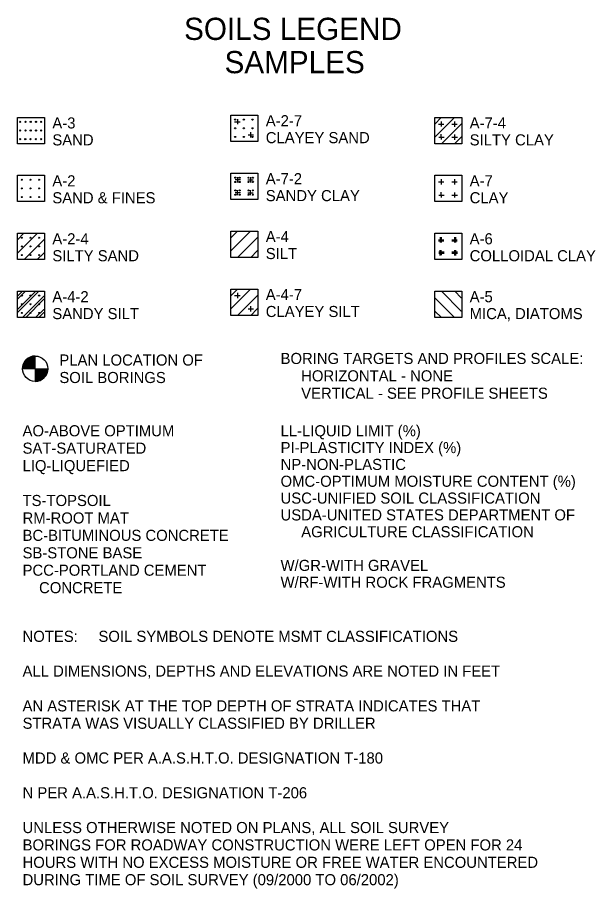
# Model space of a CAD drawing. Extents: x 1.3 to 42.5, y 0 to 21.2.
# Drawn here: x 36.22 to 42.47, y 11.81 to 21.24 of the extents above; entities that cross this region are included whole.
import ezdxf

# ---------------------------------------------------------------- set-up
doc = ezdxf.new("R2010")
doc.units = 0
doc.layers.add('SOIL-TEXT', color=7, linetype='Continuous')

msp = doc.modelspace()

# ---------------------------------------------------------------- linework, layer by layer
at = {"layer": 'SOIL-TEXT'}
for p, q in [((38.5684, 20.107), (38.6266, 20.107)), ((40.8022, 20.1541), (40.7317, 20.0819)), ((40.9453, 20.1531), (40.7317, 19.9395)), ((40.7726, 20.0823), (40.8309, 20.0823)), ((41.0164, 20.0819), (40.8041, 19.8696)), ((40.9147, 20.0819), (40.9729, 20.0819)), ((40.9453, 20.11), (40.9453, 20.0531)), ((41.0238, 20.0892), (41.0167, 20.0819)), ((38.7131, 19.9642), (38.7713, 19.9642)), ((40.7747, 19.9395), (40.833, 19.9395)), ((40.8028, 19.9146), (40.8026, 19.9715)), ((40.9173, 19.9395), (40.9756, 19.9395)), ((41.0164, 19.9395), (40.9465, 19.8696)), ((41.0238, 19.9467), (41.0167, 19.9395)), ((38.6003, 19.5082), (38.6003, 19.4513)), ((38.741, 19.5082), (38.741, 19.4513)), ((38.6309, 19.48), (38.5727, 19.48)), ((38.7104, 19.48), (38.7687, 19.48)), ((40.7726, 19.4569), (40.8309, 19.4569)), ((40.9147, 19.4564), (40.9729, 19.4564)), ((40.9453, 19.4846), (40.9453, 19.4277)), ((38.6309, 19.3401), (38.5727, 19.3401)), ((38.6003, 19.3119), (38.6003, 19.3688)), ((38.7092, 19.3401), (38.7675, 19.3401)), ((38.7398, 19.3119), (38.7398, 19.3688)), ((40.7747, 19.314), (40.833, 19.314)), ((40.8028, 19.2892), (40.8026, 19.3461)), ((40.9173, 19.3141), (40.9756, 19.3141)), ((36.291, 18.9011), (36.2204, 18.8289)), ((36.434, 18.9001), (36.2204, 18.6865)), ((38.598, 18.9247), (38.5274, 18.8525)), ((38.741, 18.9237), (38.5274, 18.7101)), ((38.8122, 18.8525), (38.5999, 18.6402)), ((38.8196, 18.8598), (38.8124, 18.8525)), ((40.9453, 18.8581), (40.9453, 18.8012)), ((40.9566, 18.8581), (40.9566, 18.8012)), ((36.5052, 18.8289), (36.2929, 18.6166)), ((36.5126, 18.8362), (36.5054, 18.8289)), ((40.7726, 18.8304), (40.8309, 18.8304)), ((40.7726, 18.819), (40.8309, 18.819)), ((40.9147, 18.8299), (40.9729, 18.8299)), ((40.9147, 18.8186), (40.9729, 18.8186)), ((36.5052, 18.6865), (36.4353, 18.6166)), ((36.5126, 18.6937), (36.5054, 18.6865)), ((38.8122, 18.7101), (38.7423, 18.6402)), ((38.8196, 18.7173), (38.8124, 18.7101)), ((40.7747, 18.699), (40.833, 18.699)), ((40.7747, 18.6876), (40.833, 18.6876)), ((40.7914, 18.6626), (40.7913, 18.7195)), ((40.8028, 18.6627), (40.8026, 18.7196)), ((40.9173, 18.699), (40.9756, 18.699)), ((40.9173, 18.6876), (40.9756, 18.6876)), ((38.598, 18.2983), (38.5274, 18.226)), ((38.741, 18.2972), (38.5274, 18.0836)), ((36.4188, 18.2746), (36.2204, 18.0762)), ((36.2739, 18.2735), (36.2211, 18.2195)), ((36.45, 18.2736), (36.2219, 18.0455)), ((36.3069, 18.2747), (36.2224, 18.1882)), ((36.5075, 18.2209), (36.279, 17.9924)), ((36.5061, 18.1873), (36.3106, 17.9918)), ((36.5126, 18.2237), (36.5084, 18.2195)), ((36.5126, 18.1911), (36.5097, 18.1882)), ((38.5684, 18.2265), (38.6266, 18.2265)), ((38.8122, 18.226), (38.5999, 18.0137)), ((38.8196, 18.2334), (38.8124, 18.226)), ((40.7336, 18.2024), (40.9459, 17.9901)), ((40.8048, 18.2736), (41.0184, 18.06)), ((40.9478, 18.2747), (41.0184, 18.2024)), ((41.0206, 18.2024), (41.0238, 18.1991)), ((38.8196, 18.0908), (38.8124, 18.0836)), ((36.5062, 18.0773), (36.4211, 17.9922)), ((36.5053, 18.0442), (36.4523, 17.9911)), ((36.5126, 18.0811), (36.5077, 18.0762)), ((36.5126, 18.0489), (36.5092, 18.0455)), ((38.7131, 18.0837), (38.7713, 18.0837)), ((38.8122, 18.0836), (38.7423, 18.0137)), ((40.7336, 18.06), (40.8035, 17.9901)), ((41.0206, 18.06), (41.0238, 18.0568)), ((36.4127, 17.4362), (36.4127, 17.5732)), ((36.4127, 17.4362), (36.2761, 17.4362)), ((36.4127, 17.4362), (36.4127, 17.4362)), ((36.4127, 17.4362), (36.4127, 17.2996)), ((36.4127, 17.4362), (36.5493, 17.4362))]:
    msp.add_line(p, q, dxfattribs=at)
for points in [[(38.5274, 20.1779), (38.8196, 20.1779), (38.8196, 19.8932), (38.5274, 19.8932)], [(36.2204, 20.1543), (36.5126, 20.1543), (36.5126, 19.8696), (36.2204, 19.8696)], [(40.7317, 20.1543), (41.0238, 20.1543), (41.0238, 19.8696), (40.7317, 19.8696)], [(36.2204, 19.5278), (36.5126, 19.5278), (36.5126, 19.2431), (36.2204, 19.2431)], [(38.5274, 19.5515), (38.8196, 19.5515), (38.8196, 19.2667), (38.5274, 19.2667)], [(40.7317, 19.5278), (41.0238, 19.5278), (41.0238, 19.2431), (40.7317, 19.2431)], [(36.2204, 18.9014), (36.5126, 18.9014), (36.5126, 18.6166), (36.2204, 18.6166)], [(38.5274, 18.925), (38.8196, 18.925), (38.8196, 18.6402), (38.5274, 18.6402)], [(40.7317, 18.9014), (41.0238, 18.9014), (41.0238, 18.6166), (40.7317, 18.6166)], [(38.5274, 18.2985), (38.8196, 18.2985), (38.8196, 18.0137), (38.5274, 18.0137)], [(36.2204, 18.2749), (36.5126, 18.2749), (36.5126, 17.9902), (36.2204, 17.9902)], [(40.7317, 18.2749), (41.0238, 18.2749), (41.0238, 17.9901), (40.7317, 17.9901)]]:
    msp.add_lwpolyline(points, close=True, dxfattribs=at)
for points in [[(38.5978, 20.1364), (38.5981, 20.1135), (38.5978, 20.0795)], [(40.802, 20.1117), (40.8023, 20.0889), (40.802, 20.0548)], [(38.7409, 19.9936), (38.7412, 19.9708), (38.7409, 19.9367)], [(40.9452, 19.9689), (40.9455, 19.9461), (40.9452, 19.912)], [(40.802, 19.4863), (40.8023, 19.4634), (40.802, 19.4294)], [(40.9452, 19.3435), (40.9455, 19.3207), (40.9452, 19.2866)], [(40.7906, 18.8597), (40.7909, 18.8369), (40.7906, 18.803)], [(40.802, 18.8598), (40.8023, 18.837), (40.802, 18.8029)], [(40.9452, 18.717), (40.9455, 18.6942), (40.9452, 18.6601)], [(40.9566, 18.7171), (40.9569, 18.6942), (40.9566, 18.66)], [(38.5978, 18.2559), (38.5981, 18.233), (38.5978, 18.199)], [(38.7409, 18.1131), (38.7412, 18.0903), (38.7409, 18.0562)]]:
    msp.add_lwpolyline(points, dxfattribs=at)
for centre, radius in [((36.2499, 20.1063), 0.0057), ((36.3068, 20.1063), 0.0057), ((36.3638, 20.1063), 0.0057), ((36.4207, 20.1063), 0.0057), ((36.4777, 20.1063), 0.0057), ((38.574, 20.1299), 0.0057), ((38.6677, 20.1299), 0.0057), ((38.7613, 20.1299), 0.0057), ((36.2499, 20.0127), 0.0057), ((36.3068, 20.0127), 0.0057), ((36.3638, 20.0127), 0.0057), ((36.4207, 20.0127), 0.0057), ((36.4777, 20.0127), 0.0057), ((38.574, 20.0363), 0.0057), ((38.6677, 20.0363), 0.0057), ((38.7613, 20.0363), 0.0057), ((36.2489, 19.9191), 0.0057), ((36.3058, 19.9191), 0.0057), ((36.3628, 19.9191), 0.0057), ((36.4197, 19.9191), 0.0057), ((36.4767, 19.9191), 0.0057), ((38.574, 19.9426), 0.0057), ((38.6677, 19.9426), 0.0057), ((38.7613, 19.9426), 0.0057), ((38.576, 19.5022), 0.0057), ((38.6225, 19.5021), 0.0057), ((38.7189, 19.5021), 0.0057), ((38.7654, 19.5022), 0.0057), ((36.267, 19.4798), 0.0057), ((36.3606, 19.4798), 0.0057), ((36.4543, 19.4798), 0.0057), ((38.576, 19.4557), 0.0057), ((38.6225, 19.4557), 0.0057), ((38.7189, 19.4557), 0.0057), ((38.7654, 19.4557), 0.0057), ((36.267, 19.3862), 0.0057), ((36.3606, 19.3862), 0.0057), ((36.4543, 19.3862), 0.0057), ((38.576, 19.3644), 0.0057), ((38.576, 19.3179), 0.0057), ((38.6225, 19.3644), 0.0057), ((38.6225, 19.318), 0.0057), ((38.7177, 19.3644), 0.0057), ((38.7177, 19.318), 0.0057), ((38.7642, 19.3644), 0.0057), ((38.7642, 19.3179), 0.0057), ((36.267, 19.2925), 0.0057), ((36.3606, 19.2925), 0.0057), ((36.4543, 19.2925), 0.0057), ((36.267, 18.8523), 0.0057), ((36.3606, 18.8523), 0.0057), ((36.4543, 18.8523), 0.0057), ((36.267, 18.7586), 0.0057), ((36.3606, 18.7586), 0.0057), ((36.4543, 18.7586), 0.0057), ((36.267, 18.665), 0.0057), ((36.3606, 18.665), 0.0057), ((36.4543, 18.665), 0.0057), ((36.268, 18.2268), 0.0057), ((36.3616, 18.2268), 0.0057), ((36.4552, 18.2268), 0.0057), ((36.268, 18.1332), 0.0057), ((36.3616, 18.1332), 0.0057), ((36.4552, 18.1332), 0.0057), ((36.268, 18.0395), 0.0057), ((36.3616, 18.0395), 0.0057), ((36.4552, 18.0395), 0.0057), ((36.4124, 17.4364), 0.1367)]:
    msp.add_circle(centre, radius, dxfattribs=at)
for radius, start, end in [(0.1367, 90.0009, 180.0009), (0.1338, 90.0009, 180.0009), (0.131, 90.0009, 180.0009), (0.1281, 90.0009, 180.0009), (0.1253, 90.0009, 180.0009), (0.1224, 90.0009, 180.0009), (0.1196, 90.0009, 180.0009), (0.1168, 90.0009, 180.0009), (0.1139, 90.0009, 180.0009), (0.1111, 90.0009, 180.0009), (0.1082, 90.0009, 180.0009), (0.1054, 90.0009, 180.0009), (0.1025, 90.0009, 180.0009), (0.0997, 90.0009, 180.0009), (0.0968, 90.0009, 180.0009), (0.094, 90.0009, 180.0009), (0.0911, 90.0009, 180.0009), (0.0883, 90.0009, 180.0009), (0.0854, 90.0009, 180.0009), (0.0826, 90.0009, 180.0009), (0.0797, 90.0009, 180.0009), (0.0769, 90.0009, 180.0009), (0.074, 90.0009, 180.0009), (0.0712, 90.0009, 180.0009), (0.0683, 90.0009, 180.0009), (0.0655, 90.0009, 180.0009), (0.0626, 90.0009, 180.0009), (0.0598, 90.0009, 180.0009), (0.057, 90.0009, 180.0009), (0.0541, 90.0009, 180.0009), (0.0513, 90.0009, 180.0009), (0.0484, 90.0009, 180.0009), (0.0456, 90.0009, 180.0009), (0.0427, 90.0009, 180.0009), (0.0399, 90.0009, 180.0009), (0.037, 90.0009, 180.0009), (0.0342, 90.0009, 180.0009), (0.0313, 90.0009, 180.0009), (0.0285, 90.0009, 180.0009), (0.0256, 90.0009, 180.0009), (0.0228, 90.0009, 180.0009), (0.0199, 90.0009, 180.0009), (0.0171, 90.0009, 180.0009), (0.0142, 90.0009, 180.0009), (0.0114, 90.0009, 180.0009), (0.00854, 90.0009, 180.0009), (0.0057, 90.0009, 180.0009), (0.00285, 90.0009, 180.0009), (0.1367, 270.0009, 0.0009), (0.1338, 270.0009, 0.0009), (0.131, 270.0009, 0.0009), (0.1281, 270.0009, 0.0009), (0.1253, 270.0009, 0.0009), (0.1224, 270.0009, 0.0009), (0.1196, 270.0009, 0.0009), (0.1168, 270.0009, 0.0009), (0.1139, 270.0009, 0.0009), (0.1111, 270.0009, 0.0009), (0.1082, 270.0009, 0.0009), (0.1054, 270.0009, 0.0009), (0.1025, 270.0009, 0.0009), (0.0997, 270.0009, 0.0009), (0.0968, 270.0009, 0.0009), (0.094, 270.0009, 0.0009), (0.0911, 270.0009, 0.0009), (0.0883, 270.0009, 0.0009), (0.0854, 270.0009, 0.0009), (0.0826, 270.0009, 0.0009), (0.0797, 270.0009, 0.0009), (0.0769, 270.0009, 0.0009), (0.074, 270.0009, 0.0009), (0.0712, 270.0009, 0.0009), (0.0683, 270.0009, 0.0009), (0.0655, 270.0009, 0.0009), (0.0626, 270.0009, 0.0009), (0.0598, 270.0009, 0.0009), (0.057, 270.0009, 0.0009), (0.0541, 270.0009, 0.0009), (0.0513, 270.0009, 0.0009), (0.0484, 270.0009, 0.0009), (0.0456, 270.0009, 0.0009), (0.0427, 270.0009, 0.0009), (0.0399, 270.0009, 0.0009), (0.037, 270.0009, 0.0009), (0.0342, 270.0009, 0.0009), (0.0313, 270.0009, 0.0009), (0.0285, 270.0009, 0.0009), (0.0256, 270.0009, 0.0009), (0.0228, 270.0009, 0.0009), (0.0199, 270.0009, 0.0009), (0.0171, 270.0009, 0.0009), (0.0142, 270.0009, 0.0009), (0.0114, 270.0009, 0.0009), (0.00854, 270.0009, 0.0009), (0.0057, 270.0009, 0.0009), (0.00285, 270.0009, 0.0009)]:
    msp.add_arc((36.4124, 17.4364), radius, start, end, dxfattribs=at)

# ---------------------------------------------------------------- texts
for s, height, p in [('SOILS LEGEND', 0.24, (38.0217, 20.992)), ('SAMPLES', 0.24, (38.4591, 20.632)), ('A-2-7', 0.12, (38.9049, 20.0584)), ('A-3', 0.12, (36.5979, 20.0344)), ('A-7-4', 0.12, (41.1089, 20.0344)), ('SAND', 0.12, (36.5979, 19.8514)), ('CLAYEY SAND', 0.12, (38.9049, 19.8754)), ('SILTY CLAY', 0.12, (41.1089, 19.8514)), ('A-2', 0.12, (36.5979, 19.4084)), ('A-7-2', 0.12, (38.9049, 19.4314)), ('A-7', 0.12, (41.1089, 19.4084)), ('SAND & FINES', 0.12, (36.5979, 19.2254)), ('SANDY CLAY', 0.12, (38.9049, 19.2484)), ('CLAY', 0.12, (41.1089, 19.2254)), ('A-2-4', 0.12, (36.5979, 18.7814)), ('A-4', 0.12, (38.9049, 18.8054)), ('A-6', 0.12, (41.1089, 18.7814)), ('SILTY SAND', 0.12, (36.5979, 18.5984)), ('SILT', 0.12, (38.9049, 18.6224)), ('COLLOIDAL CLAY', 0.12, (41.1089, 18.5984)), ('A-4-7', 0.12, (38.9049, 18.1784)), ('A-4-2', 0.12, (36.5979, 18.1554)), ('A-5', 0.12, (41.1089, 18.1554)), ('SANDY SILT', 0.12, (36.5979, 17.9724)), ('CLAYEY SILT', 0.12, (38.9049, 17.9954)), ('MICA, DIATOMS', 0.12, (41.1089, 17.9724)), ('PLAN LOCATION OF ', 0.12, (36.6739, 17.4704)), ('BORING TARGETS AND PROFILES SCALE:', 0.12, (39.0649, 17.4874)), ('SOIL BORINGS', 0.12, (36.6739, 17.2814)), ('     HORIZONTAL - NONE', 0.12, (39.0649, 17.2994)), ('     VERTICAL - SEE PROFILE SHEETS', 0.12, (39.0649, 17.1114)), ('AO-ABOVE OPTIMUM', 0.12, (36.2759, 16.7054)), ('LL-LIQUID LIMIT (%)', 0.12, (39.0649, 16.7054)), ('SAT-SATURATED', 0.12, (36.2759, 16.5174)), ('PI-PLASTICITY INDEX (%)', 0.12, (39.0649, 16.5234)), ('LIQ-LIQUEFIED', 0.12, (36.2759, 16.3284)), ('NP-NON-PLASTIC', 0.12, (39.0649, 16.3414)), ('OMC-OPTIMUM MOISTURE CONTENT (%)', 0.12, (39.0649, 16.1594)), ('TS-TOPSOIL', 0.12, (36.2759, 15.9514)), ('USC-UNIFIED SOIL CLASSIFICATION', 0.12, (39.0649, 15.9774)), ('RM-ROOT MAT', 0.12, (36.2759, 15.7624)), ('USDA-UNITED STATES DEPARTMENT OF', 0.12, (39.0649, 15.7954)), ('     AGRICULTURE CLASSIFICATION', 0.12, (39.0649, 15.6134)), ('BC-BITUMINOUS CONCRETE', 0.12, (36.2759, 15.5744)), ('SB-STONE BASE', 0.12, (36.2759, 15.3854)), ('W/GR-WITH GRAVEL', 0.12, (39.0649, 15.2494)), ('PCC-PORTLAND CEMENT', 0.12, (36.2759, 15.1974)), ('W/RF-WITH ROCK FRAGMENTS', 0.12, (39.0649, 15.0674)), ('    CONCRETE', 0.12, (36.2759, 15.0084)), ('NOTES:     SOIL SYMBOLS DENOTE MSMT CLASSIFICATIONS', 0.12, (36.2759, 14.4824)), ('ALL DIMENSIONS, DEPTHS AND ELEVATIONS ARE NOTED IN FEET', 0.12, (36.2759, 14.1064)), ('AN ASTERISK AT THE TOP DEPTH OF STRATA INDICATES THAT ', 0.12, (36.2759, 13.7304)), ('STRATA WAS VISUALLY CLASSIFIED BY DRILLER', 0.12, (36.2759, 13.5424)), ('MDD & OMC PER A.A.S.H.T.O. DESIGNATION T-180', 0.12, (36.2759, 13.1664)), ('N PER A.A.S.H.T.O. DESIGNATION T-206', 0.12, (36.2759, 12.7904)), ('UNLESS OTHERWISE NOTED ON PLANS, ALL SOIL SURVEY ', 0.12, (36.2759, 12.4144)), ('BORINGS FOR ROADWAY CONSTRUCTION WERE LEFT OPEN FOR 24 ', 0.12, (36.2759, 12.2264)), ('HOURS WITH NO EXCESS MOISTURE OR FREE WATER ENCOUNTERED ', 0.12, (36.2759, 12.0384)), ('DURING TIME OF SOIL SURVEY (09/2000 TO 06/2002)', 0.12, (36.2759, 11.8504))]:
    msp.add_text(s, height=height, dxfattribs=at).set_placement(p)

doc.saveas('drawing.dxf')
